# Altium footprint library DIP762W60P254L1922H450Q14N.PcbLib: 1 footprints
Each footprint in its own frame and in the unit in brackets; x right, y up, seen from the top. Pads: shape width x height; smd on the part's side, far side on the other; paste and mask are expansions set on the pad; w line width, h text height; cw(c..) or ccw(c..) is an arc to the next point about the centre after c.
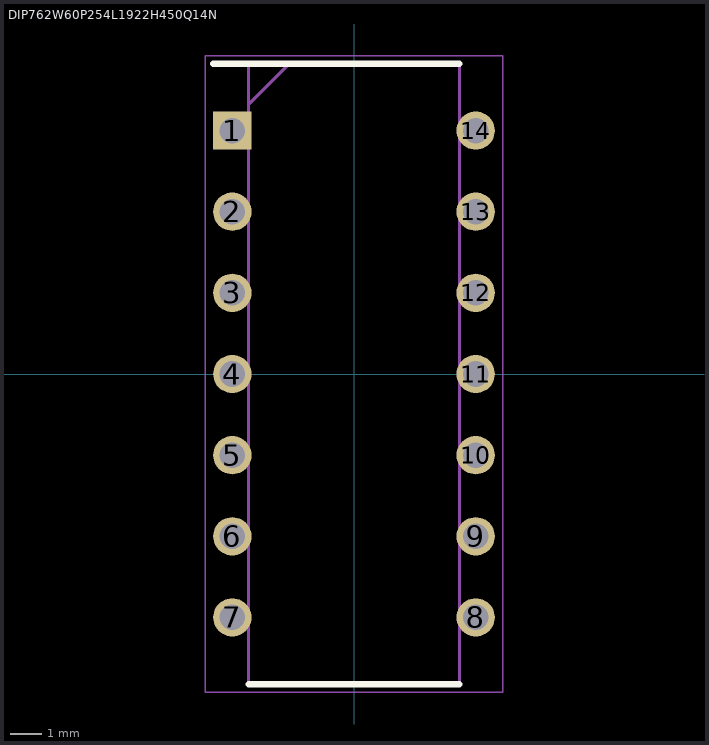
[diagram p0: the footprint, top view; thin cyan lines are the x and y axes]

## DIP762W60P254L1922H450Q14N [mm]
pads (14):
  rect 1.2x1.2 / inner round 1.2 / far side rect 1.2x1.2 hole 0.8: 1(-3.81,7.62)
  round 1.2 hole 0.8: 2(-3.81,5.08) 3(-3.81,2.54) 4(-3.81,0) 5(-3.81,-2.54) 6(-3.81,-5.08) 7(-3.81,-7.62) 8(3.81,-7.62) 9(3.81,-5.08) 10(3.81,-2.54) 11(3.81,0) 12(3.81,2.54) 13(3.81,5.08) 14(3.81,7.62)
Top Overlay:
  lines w0.2: -4.41,9.71 3.3,9.71 ; -3.3,-9.71 3.3,-9.71
Mechanical 15:
  lines w0.1: -3.3,8.44 -2.03,9.71 ; -3.3,-9.71 3.3,-9.71 3.3,9.71 -3.3,9.71 -3.3,-9.71
Mechanical 20:
  lines w0.05: -4.66,-9.96 4.66,-9.96 4.66,9.96 -4.66,9.96 -4.66,-9.96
